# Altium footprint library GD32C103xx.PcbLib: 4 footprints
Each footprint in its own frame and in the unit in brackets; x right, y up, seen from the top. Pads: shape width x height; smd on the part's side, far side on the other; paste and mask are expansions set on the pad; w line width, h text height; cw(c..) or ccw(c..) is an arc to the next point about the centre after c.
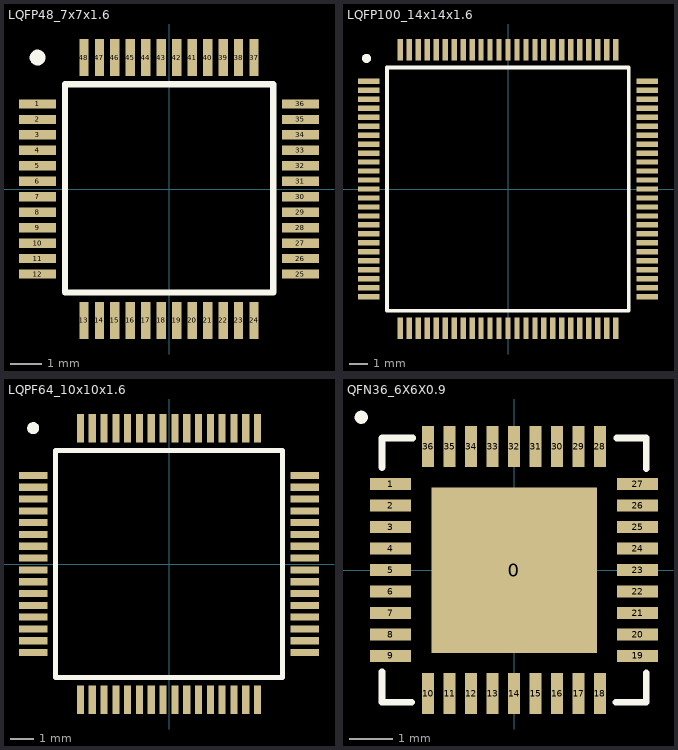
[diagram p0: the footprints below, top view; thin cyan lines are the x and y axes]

## LQFP48_7x7x1.6 [mm]
pads (48):
  rect 1.2x0.3 smd: 1(-4.25,2.75) 2(-4.25,2.25) 3(-4.25,1.75) 4(-4.25,1.25) 5(-4.25,0.75) 6(-4.25,0.25) 7(-4.25,-0.25) 8(-4.25,-0.75) 9(-4.25,-1.25) 10(-4.25,-1.75) 11(-4.25,-2.25) 12(-4.25,-2.75) 25(4.25,-2.75) 26(4.25,-2.25) 27(4.25,-1.75) 28(4.25,-1.25) 29(4.25,-0.75) 30(4.25,-0.25) 31(4.25,0.25) 32(4.25,0.75) 33(4.25,1.25) 34(4.25,1.75) 35(4.25,2.25) 36(4.25,2.75)
  rect 0.3x1.2 smd: 13(-2.75,-4.25) 14(-2.25,-4.25) 15(-1.75,-4.25) 16(-1.25,-4.25) 17(-0.75,-4.25) 18(-0.25,-4.25) 19(0.25,-4.25) 20(0.75,-4.25) 21(1.25,-4.25) 22(1.75,-4.25) 23(2.25,-4.25) 24(2.75,-4.25) 37(2.75,4.25) 38(2.25,4.25) 39(1.75,4.25) 40(1.25,4.25) 41(0.75,4.25) 42(0.25,4.25) 43(-0.25,4.25) 44(-0.75,4.25) 45(-1.25,4.25) 46(-1.75,4.25) 47(-2.25,4.25) 48(-2.75,4.25)
Top Overlay:
  circle w0.254: c-4.25,4.25 r0.127
  lines w0.203: -3.361,-3.346 -3.361,3.385 3.37,3.385 3.37,-3.346 -3.361,-3.346
3D body "TSQFP50P900X900X160-48N.step": height 1.6, standoff 0, extent -4.5,-4.5 4.5,4.5

## LQFP100_14x14x1.6 [mm]
pads (100):
  rect 1.2x0.3 smd: 1(-7.75,6) 2(-7.75,5.5) 3(-7.75,5) 4(-7.75,4.5) 5(-7.75,4) 6(-7.75,3.5) 7(-7.75,3) 8(-7.75,2.5) 9(-7.75,2) 10(-7.75,1.5) 11(-7.75,1) 12(-7.75,0.5) 13(-7.75,0) 14(-7.75,-0.5) 15(-7.75,-1) 16(-7.75,-1.5) 17(-7.75,-2) 18(-7.75,-2.5) 19(-7.75,-3) 20(-7.75,-3.5) 21(-7.75,-4) 22(-7.75,-4.5) 23(-7.75,-5) 24(-7.75,-5.5) 25(-7.75,-6) 51(7.75,-6) 52(7.75,-5.5) 53(7.75,-5) 54(7.75,-4.5) 55(7.75,-4) 56(7.75,-3.5) 57(7.75,-3) 58(7.75,-2.5) 59(7.75,-2) 60(7.75,-1.5) 61(7.75,-1) 62(7.75,-0.5) 63(7.75,0) 64(7.75,0.5) 65(7.75,1) 66(7.75,1.5) 67(7.75,2) 68(7.75,2.5) 69(7.75,3) 70(7.75,3.5) 71(7.75,4) 72(7.75,4.5) 73(7.75,5) 74(7.75,5.5) 75(7.75,6)
  rect 0.3x1.2 smd: 26(-6,-7.75) 27(-5.5,-7.75) 28(-5,-7.75) 29(-4.5,-7.75) 30(-4,-7.75) 31(-3.5,-7.75) 32(-3,-7.75) 33(-2.5,-7.75) 34(-2,-7.75) 35(-1.5,-7.75) 36(-1,-7.75) 37(-0.5,-7.75) 38(0,-7.75) 39(0.5,-7.75) 40(1,-7.75) 41(1.5,-7.75) 42(2,-7.75) 43(2.5,-7.75) 44(3,-7.75) 45(3.5,-7.75) 46(4,-7.75) 47(4.5,-7.75) 48(5,-7.75) 49(5.5,-7.75) 50(6,-7.75) 76(6,7.75) 77(5.5,7.75) 78(5,7.75) 79(4.5,7.75) 80(4,7.75) 81(3.5,7.75) 82(3,7.75) 83(2.5,7.75) 84(2,7.75) 85(1.5,7.75) 86(1,7.75) 87(0.5,7.75) 88(0,7.75) 89(-0.5,7.75) 90(-1,7.75) 91(-1.5,7.75) 92(-2,7.75) 93(-2.5,7.75) 94(-3,7.75) 95(-3.5,7.75) 96(-4,7.75) 97(-4.5,7.75) 98(-5,7.75) 99(-5.5,7.75) 100(-6,7.75)
Top Overlay:
  circle w0.254: c-7.877,7.27 r0.127
  lines w0.203: -6.734,-6.782 -6.734,6.762 6.728,6.762 6.728,-6.782 -6.734,-6.782
3D body "TSQFP50P1600X1600X160-100N.step": height 1.6, standoff 0, extent -8,-8 8,8

## LQPF64_10x10x1.6 [mm]
pads (64):
  rect 1.2x0.3 smd: 1(-5.75,3.75) 2(-5.75,3.25) 3(-5.75,2.75) 4(-5.75,2.25) 5(-5.75,1.75) 6(-5.75,1.25) 7(-5.75,0.75) 8(-5.75,0.25) 9(-5.75,-0.25) 10(-5.75,-0.75) 11(-5.75,-1.25) 12(-5.75,-1.75) 13(-5.75,-2.25) 14(-5.75,-2.75) 15(-5.75,-3.25) 16(-5.75,-3.75) 33(5.75,-3.75) 34(5.75,-3.25) 35(5.75,-2.75) 36(5.75,-2.25) 37(5.75,-1.75) 38(5.75,-1.25) 39(5.75,-0.75) 40(5.75,-0.25) 41(5.75,0.25) 42(5.75,0.75) 43(5.75,1.25) 44(5.75,1.75) 45(5.75,2.25) 46(5.75,2.75) 47(5.75,3.25) 48(5.75,3.75)
  rect 0.3x1.2 smd: 17(-3.75,-5.75) 18(-3.25,-5.75) 19(-2.75,-5.75) 20(-2.25,-5.75) 21(-1.75,-5.75) 22(-1.25,-5.75) 23(-0.75,-5.75) 24(-0.25,-5.75) 25(0.25,-5.75) 26(0.75,-5.75) 27(1.25,-5.75) 28(1.75,-5.75) 29(2.25,-5.75) 30(2.75,-5.75) 31(3.25,-5.75) 32(3.75,-5.75) 49(3.75,5.75) 50(3.25,5.75) 51(2.75,5.75) 52(2.25,5.75) 53(1.75,5.75) 54(1.25,5.75) 55(0.75,5.75) 56(0.25,5.75) 57(-0.25,5.75) 58(-0.75,5.75) 59(-1.25,5.75) 60(-1.75,5.75) 61(-2.25,5.75) 62(-2.75,5.75) 63(-3.25,5.75) 64(-3.75,5.75)
Top Overlay:
  circle w0.254: c-5.75,5.75 r0.127
  lines w0.203: -4.801,-4.801 4.801,-4.801 4.801,4.801 -4.801,4.801 -4.801,-4.801
3D body "TSQFP50P1200X1200X160-64N.step": height 1.6, standoff 0, extent -6,-6 6,6

## QFN36_6X6X0.9 [mm]
pads (37):
  rect 3.85x3.85 smd: 0(0,0)
  rect 0.95x0.28 smd: 1(-2.875,2) 2(-2.875,1.5) 3(-2.875,1) 4(-2.875,0.5) 5(-2.875,0) 6(-2.875,-0.5) 7(-2.875,-1) 8(-2.875,-1.5) 9(-2.875,-2) 19(2.875,-2) 20(2.875,-1.5) 21(2.875,-1) 22(2.875,-0.5) 23(2.875,0) 24(2.875,0.5) 25(2.875,1) 26(2.875,1.5) 27(2.875,2)
  rect 0.28x0.95 smd: 10(-2,-2.875) 11(-1.5,-2.875) 12(-1,-2.875) 13(-0.5,-2.875) 14(0,-2.875) 15(0.5,-2.875) 16(1,-2.875) 17(1.5,-2.875) 18(2,-2.875) 28(2,2.875) 29(1.5,2.875) 30(1,2.875) 31(0.5,2.875) 32(0,2.875) 33(-0.5,2.875) 34(-1,2.875) 35(-1.5,2.875) 36(-2,2.875)
Top Overlay:
  circle w0.152: c-3.556,3.556 r0.076
  lines w0.152: -3.073,-2.362 -3.073,-3.073 -2.388,-3.073 ; -3.073,2.388 -3.073,3.073 -2.362,3.073 ; 2.362,-3.073 3.073,-3.073 3.073,-2.388 ; 2.388,3.073 3.073,3.073 3.073,2.362
3D body "QFN50P600X600X90_HS-37N.step": height 0.9, standoff 0, extent -3.051,-3.051 3.051,3.051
